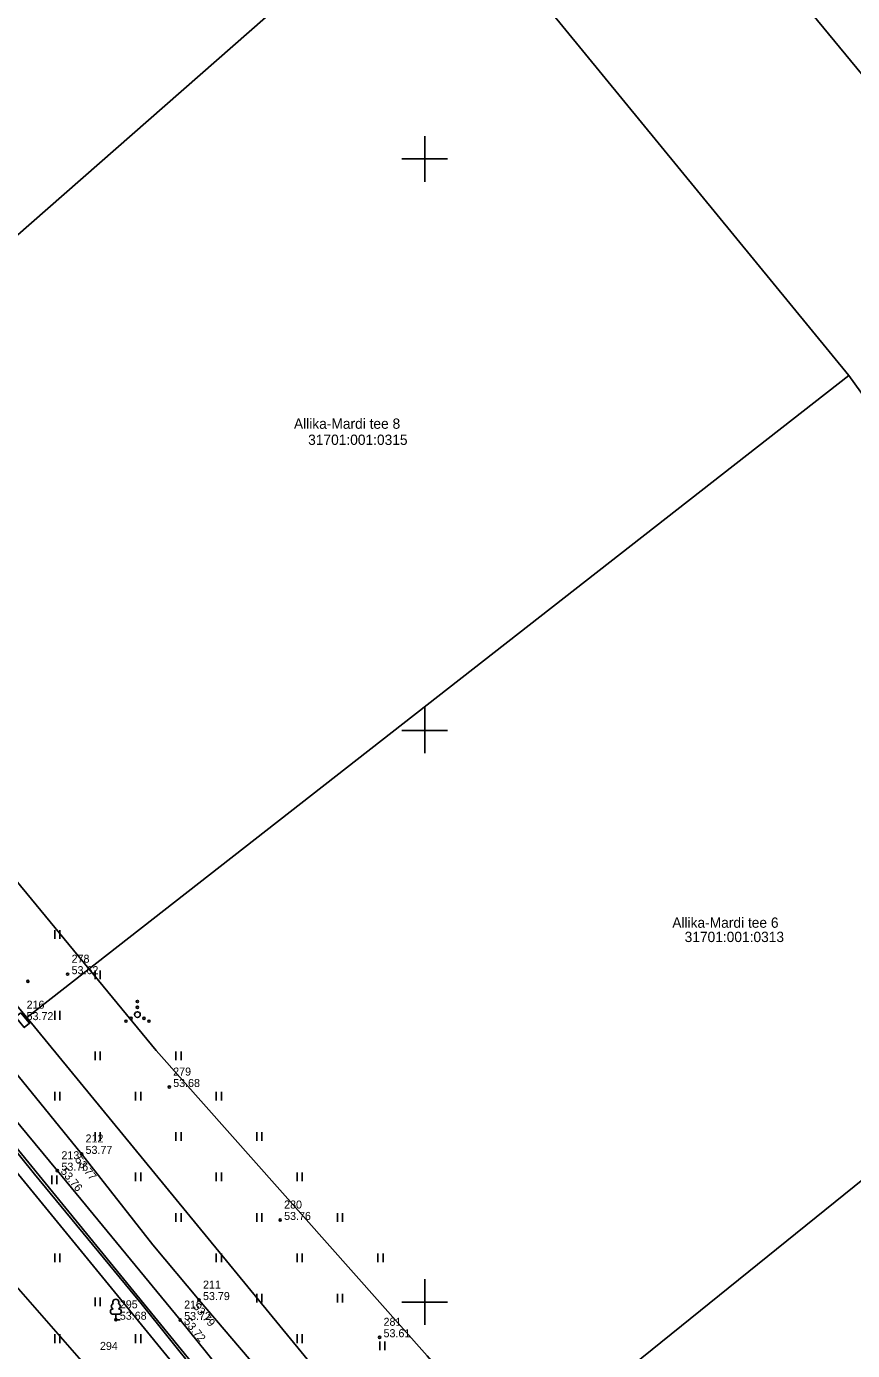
# Model space of a CAD drawing. Extents: x 538599 to 541973, y 6559689 to 6564516.
# Drawn here: x 540465.1 to 540537.4, y 6561345.8 to 6561461.6 of the extents above; entities that cross this region are included whole.
import ezdxf

# ---------------------------------------------------------------- set-up
doc = ezdxf.new("R2010")
doc.units = 0
for name, color, linetype in [('ELRAJATISMP', 7, 'Continuous'), ('HALJASTUS', 7, 'Continuous'), ('KORGUS-EH2000', 7, 'Continuous'), ('KPKAABEL', 7, 'Continuous'), ('MOOTKORG-EH2000', 7, 'Continuous'), ('MOOTMPUNKT', 7, 'Continuous'), ('MOOTNR', 7, 'Continuous'), ('MOOTPIIR', 7, 'Continuous'), ('MPKAABEL', 7, 'Continuous'), ('PIIR', 7, 'Continuous'), ('PUU', 7, 'Continuous'), ('TEE', 7, 'Continuous'), ('VORK', 7, 'Continuous')]:
    doc.layers.add(name, color=color, linetype=linetype)

msp = doc.modelspace()

# ---------------------------------------------------------------- linework, layer by layer
at = {"layer": 'ELRAJATISMP'}
msp.add_lwpolyline([(540464.65, 6561375.31), (540465.41, 6561374.39), (540464.94, 6561374.01), (540464.19, 6561374.94)], close=True, dxfattribs=at)
at = {"layer": 'HALJASTUS'}
for p, q in [((540467.61, 6561382.53), (540467.61, 6561381.77)), ((540468.07, 6561382.53), (540468.07, 6561381.77)), ((540471.15, 6561379), (540471.15, 6561378.23)), ((540471.6, 6561379), (540471.6, 6561378.23)), ((540467.61, 6561375.46), (540467.61, 6561374.7)), ((540468.07, 6561375.46), (540468.07, 6561374.7)), ((540471.15, 6561371.92), (540471.15, 6561371.16)), ((540471.6, 6561371.92), (540471.6, 6561371.16)), ((540478.22, 6561371.92), (540478.22, 6561371.16)), ((540478.67, 6561371.92), (540478.67, 6561371.16)), ((540467.61, 6561368.39), (540467.61, 6561367.63)), ((540468.07, 6561368.39), (540468.07, 6561367.63)), ((540474.68, 6561368.39), (540474.68, 6561367.63)), ((540475.14, 6561368.39), (540475.14, 6561367.63)), ((540481.75, 6561368.39), (540481.75, 6561367.63)), ((540482.21, 6561368.39), (540482.21, 6561367.63)), ((540471.15, 6561364.85), (540471.15, 6561364.09)), ((540471.6, 6561364.85), (540471.6, 6561364.09)), ((540478.22, 6561364.85), (540478.22, 6561364.09)), ((540478.67, 6561364.85), (540478.67, 6561364.09)), ((540485.29, 6561364.85), (540485.29, 6561364.09)), ((540485.74, 6561364.85), (540485.74, 6561364.09)), ((540467.35, 6561361.06), (540467.35, 6561360.3)), ((540467.8, 6561361.06), (540467.8, 6561360.3)), ((540474.68, 6561361.32), (540474.68, 6561360.56)), ((540475.14, 6561361.32), (540475.14, 6561360.56)), ((540481.75, 6561361.32), (540481.75, 6561360.56)), ((540482.21, 6561361.32), (540482.21, 6561360.56)), ((540488.82, 6561361.32), (540488.82, 6561360.56)), ((540489.28, 6561361.32), (540489.28, 6561360.56)), ((540478.22, 6561357.78), (540478.22, 6561357.02)), ((540478.67, 6561357.78), (540478.67, 6561357.02)), ((540485.29, 6561357.78), (540485.29, 6561357.02)), ((540485.74, 6561357.78), (540485.74, 6561357.02)), ((540492.36, 6561357.78), (540492.36, 6561357.02)), ((540492.81, 6561357.78), (540492.81, 6561357.02)), ((540467.61, 6561354.25), (540467.61, 6561353.49)), ((540468.07, 6561354.25), (540468.07, 6561353.49)), ((540481.75, 6561354.25), (540481.75, 6561353.49)), ((540482.21, 6561354.25), (540482.21, 6561353.49)), ((540488.82, 6561354.25), (540488.82, 6561353.49)), ((540489.28, 6561354.25), (540489.28, 6561353.49)), ((540495.89, 6561354.25), (540495.89, 6561353.49)), ((540496.35, 6561354.25), (540496.35, 6561353.49)), ((540471.15, 6561350.41), (540471.15, 6561349.65)), ((540471.6, 6561350.41), (540471.6, 6561349.65)), ((540485.29, 6561350.71), (540485.29, 6561349.95)), ((540485.74, 6561350.71), (540485.74, 6561349.95)), ((540492.36, 6561350.71), (540492.36, 6561349.95)), ((540492.81, 6561350.71), (540492.81, 6561349.95)), ((540467.61, 6561347.18), (540467.61, 6561346.41)), ((540468.07, 6561347.18), (540468.07, 6561346.41)), ((540474.68, 6561347.18), (540474.68, 6561346.41)), ((540475.14, 6561347.18), (540475.14, 6561346.41)), ((540488.82, 6561347.18), (540488.82, 6561346.41)), ((540489.28, 6561347.18), (540489.28, 6561346.41)), ((540496.05, 6561346.56), (540496.05, 6561345.8)), ((540496.51, 6561346.56), (540496.51, 6561345.8))]:
    msp.add_line(p, q, dxfattribs=at)
for centre, radius in [((540465.26, 6561378.06), 0.1), ((540474.85, 6561375.14), 0.25), ((540474.85, 6561376.29), 0.1), ((540474.85, 6561375.79), 0.1), ((540473.85, 6561374.57), 0.1), ((540474.29, 6561374.82), 0.1), ((540475.42, 6561374.82), 0.1), ((540475.85, 6561374.57), 0.1)]:
    msp.add_circle(centre, radius, dxfattribs=at)
at = {"layer": 'KORGUS-EH2000'}
for centre in [(540468.74, 6561378.68), (540477.64, 6561368.81), (540469.96, 6561362.96), (540467.85, 6561361.49), (540487.34, 6561357.18), (540480.24, 6561350.17), (540478.59, 6561348.43), (540496.04, 6561346.92)]:
    msp.add_circle(centre, 0.1, dxfattribs=at)
at = {"layer": 'KPKAABEL'}
msp.add_lwpolyline([(540612.71, 6561251.64), (540589.75, 6561235.92), (540575.11, 6561226.32), (540574.31, 6561226.49), (540572.81, 6561227.65), (540566.99, 6561234.12), (540563.29, 6561239.03), (540553.8, 6561251.29), (540538.41, 6561271.22), (540529.49, 6561282.51), (540526.27, 6561286.88), (540510.56, 6561306.2), (540484.62, 6561338.57), (540463.55, 6561364.4), (540438.89, 6561393.7), (540425.44, 6561409.21), (540424.92, 6561409.46), (540423.73, 6561408.81), (540421.72, 6561406.34), (540419.82, 6561404.72)], dxfattribs=at)
at = {"layer": 'MOOTMPUNKT'}
for centre in [(540468.74, 6561378.68), (540477.64, 6561368.81), (540469.96, 6561362.96), (540467.85, 6561361.49), (540487.34, 6561357.18), (540480.24, 6561350.17), (540472.96, 6561348.45), (540478.59, 6561348.43), (540496.04, 6561346.92)]:
    msp.add_circle(centre, 0.1, dxfattribs=at)
at = {"layer": 'MOOTPIIR'}
for points in [[(540611.81, 6561347.63), (540600.55, 6561344.05), (540588.99, 6561338.31), (540579.51, 6561329.75), (540567.37, 6561324.71), (540557.3, 6561315.5), (540537.55, 6561303.29), (540525.23, 6561316.05), (540500.22, 6561345.28), (540476.49, 6561372), (540449.03, 6561405.28), (540428.79, 6561428.29), (540413.02, 6561448.22), (540405.1, 6561459.89), (540393.81, 6561473.15)], [(540384.89, 6561443.84), (540403.97, 6561422.47), (540424.3, 6561399.7), (540444.64, 6561376.93), (540453.18, 6561363.99), (540470.99, 6561343.69), (540492.69, 6561318.98), (540511.77, 6561294.34), (540521.97, 6561279.18), (540525.59, 6561267.95), (540536.49, 6561252.79), (540542.77, 6561231.93), (540526.6, 6561219.05), (540510.62, 6561213.47), (540498.26, 6561199.2), (540484.56, 6561192.98), (540479.62, 6561185.62), (540478.41, 6561178.33), (540490.46, 6561165.83), (540493.58, 6561162.6), (540531.11, 6561187.91), (540582.87, 6561222.82), (540621.74, 6561247.75)]]:
    msp.add_lwpolyline(points, dxfattribs=at)
at = {"layer": 'MPKAABEL'}
msp.add_lwpolyline([(540496.22, 6561323.66), (540475.17, 6561349.87), (540465.85, 6561361.18), (540459.23, 6561369.37), (540458.44, 6561368.9), (540458.85, 6561369.82), (540450.37, 6561379.81), (540440.39, 6561391.62), (540426.57, 6561407.61), (540425.32, 6561409.05), (540424.93, 6561409.23), (540424.03, 6561408.75), (540421.85, 6561406.21), (540419.93, 6561404.6)], dxfattribs=at)
at = {"layer": 'PIIR'}
for points in [[(540290.72, 6561746.68), (540427.24, 6561588.74), (540493.94, 6561511.13), (540543.58, 6561450.93), (540540.24, 6561448.03), (540578.89, 6561396.62), (540600.99, 6561365.08), (540659.54, 6561279.7), (540697.59, 6561212.89), (540728.6, 6561157.63), (540756.94, 6561107.21), (540762.6, 6561098.5), (540765.3, 6561101.59), (540815.83, 6561019.53), (540863.6, 6560935.22), (540880.61, 6560910.09), (540903.4, 6560875.14), (540927.11, 6560842.51), (540955.71, 6560805.99), (540982.2, 6560772.63), (541049.12, 6560693.03)], [(541045.65, 6560666.8), (540964.7, 6560765.19), (540868.94, 6560895.75), (540756.19, 6561084.56), (540744.95, 6561099.98), (540716.4, 6561150.76), (540687.02, 6561204.55), (540646.74, 6561272.89), (540640.63, 6561283.66), (540606.26, 6561333.96), (540569.6, 6561385.93), (540537.11, 6561431.06), (540500.82, 6561475.34), (540460.86, 6561522.64), (540423.13, 6561566.69), (540380.29, 6561616.49), (540342.1, 6561660.8)]]:
    msp.add_lwpolyline(points, dxfattribs=at)
for points in [[(540493.94, 6561511.13), (540576.02, 6561585.01), (540701.8, 6561446.25), (540600.99, 6561365.08), (540578.89, 6561396.62), (540540.24, 6561448.03), (540543.58, 6561450.93)], [(540491.21, 6561183.5), (540566.07, 6561233.36), (540528.84, 6561281.85), (540494.34, 6561324.62), (540458.27, 6561368.69), (540424.68, 6561408.57), (540384.55, 6561455.73), (540346.17, 6561499.11), (540330.12, 6561517.14), (540337.36, 6561523.32), (540348.28, 6561532.96), (540364.11, 6561514.94), (540353.14, 6561505.27), (540391.51, 6561461.86), (540431.74, 6561414.74), (540465.17, 6561374.89), (540501.31, 6561330.86), (540535.92, 6561287.97), (540573.77, 6561238.75), (540640.63, 6561283.66), (540646.74, 6561272.89), (540499, 6561174.36)], [(540391.51, 6561461.86), (540460.86, 6561522.64), (540500.82, 6561475.34), (540431.74, 6561414.74)], [(540431.74, 6561414.74), (540500.82, 6561475.34), (540537.11, 6561431.06), (540465.17, 6561374.89)], [(540465.17, 6561374.89), (540537.11, 6561431.06), (540569.6, 6561385.93), (540501.31, 6561330.86)], [(540501.31, 6561330.86), (540569.6, 6561385.93), (540606.26, 6561333.96), (540535.92, 6561287.97)], [(540384.73, 6561304.57), (540458.27, 6561368.69), (540494.34, 6561324.62), (540422.29, 6561261.69)]]:
    msp.add_lwpolyline(points, close=True, dxfattribs=at)
at = {"layer": 'PUU'}
for p, q in [((540473.2, 6561348.93), (540472.72, 6561348.93)), ((540472.96, 6561348.45), (540472.96, 6561348.93)), ((540473.34, 6561348.45), (540472.96, 6561348.45))]:
    msp.add_line(p, q, dxfattribs=at)
for centre, radius, start, end in [((540472.79, 6561349.63), 0.233, 109.0217, 253.1415), ((540472.96, 6561349.97), 0.277, 332.5799, 207.4201), ((540473.13, 6561349.63), 0.233, 286.8508, 70.9859), ((540472.72, 6561349.17), 0.238, 90.0016, 269.3953), ((540473.2, 6561349.17), 0.238, 270.6047, 89.9984)]:
    msp.add_arc(centre, radius, start, end, dxfattribs=at)
at = {"layer": 'TEE'}
for points in [[(540488.15, 6561336.58), (540478.59, 6561348.43), (540467.85, 6561361.49), (540459.32, 6561371.76), (540451.23, 6561381.75), (540441.06, 6561393.63), (540438.74, 6561396.54), (540432.54, 6561404.86), (540428.83, 6561409.26), (540422.19, 6561416.81), (540412.69, 6561428.77), (540402.74, 6561440.04), (540395.61, 6561447.09), (540392.51, 6561450.44), (540382.51, 6561461.31)], [(540388.6, 6561459.28), (540394.61, 6561452.94), (540404.96, 6561441.5), (540414.41, 6561430.92), (540424.76, 6561418.49), (540434.32, 6561406.77), (540435.95, 6561404.71), (540443.75, 6561395.53), (540453.23, 6561383.82), (540461.24, 6561373.67), (540469.96, 6561362.96), (540476.2, 6561354.99), (540480.24, 6561350.17), (540490.34, 6561338.33)]]:
    msp.add_lwpolyline(points, dxfattribs=at)
at = {"layer": 'VORK'}
for p, q in [((540500, 6561452), (540500, 6561448)), ((540498, 6561450), (540502, 6561450)), ((540500, 6561402), (540500, 6561398)), ((540498, 6561400), (540502, 6561400)), ((540500, 6561352), (540500, 6561348)), ((540498, 6561350), (540502, 6561350))]:
    msp.add_line(p, q, dxfattribs=at)

# ---------------------------------------------------------------- texts
at = {"layer": 'KORGUS-EH2000'}
for s, p in [('53.62', (540469.09, 6561378.68)), ('53.68', (540477.98, 6561368.81)), ('53.76', (540487.69, 6561357.18)), ('53.61', (540496.39, 6561346.92))]:
    msp.add_text(s, height=0.7, dxfattribs=at).set_placement(p)
for s, rotation, p in [('53.77', 308.0609, (540469.34, 6561362.42)), ('53.76', 309.4141, (540468.08, 6561361.4)), ('53.79', 310.4823, (540479.67, 6561349.56)), ('53.72', 308.9107, (540478.87, 6561348.26))]:
    msp.add_text(s, height=0.7, rotation=rotation, dxfattribs=at).set_placement(p)
at = {"layer": 'MOOTKORG-EH2000'}
for s, p in [('53.62', (540469.09, 6561378.68)), ('53.72', (540465.15, 6561374.66)), ('53.68', (540477.98, 6561368.81)), ('53.77', (540470.31, 6561362.96)), ('53.76', (540468.2, 6561361.49)), ('53.76', (540487.69, 6561357.18)), ('53.79', (540480.59, 6561350.17)), ('53.68', (540473.31, 6561348.45)), ('53.72', (540478.94, 6561348.43)), ('53.61', (540496.39, 6561346.92))]:
    msp.add_text(s, height=0.7, dxfattribs=at).set_placement(p)
at = {"layer": 'MOOTNR'}
for s, p in [('278', (540469.09, 6561379.68)), ('216', (540465.15, 6561375.66)), ('279', (540477.98, 6561369.81)), ('212', (540470.31, 6561363.96)), ('213', (540468.2, 6561362.49)), ('280', (540487.69, 6561358.18)), ('211', (540480.59, 6561351.17)), ('295', (540473.31, 6561349.45)), ('210', (540478.94, 6561349.43)), ('281', (540496.39, 6561347.92)), ('294', (540471.57, 6561345.81))]:
    msp.add_text(s, height=0.7, dxfattribs=at).set_placement(p)
at = {"layer": 'PIIR'}
for s, p in [('Allika-Mardi tee 8', (540488.55, 6561426.39)), ('31701:001:0315', (540489.79, 6561424.98)), ('Allika-Mardi tee 6', (540521.66, 6561382.74)), ('31701:001:0313', (540522.74, 6561381.49))]:
    msp.add_text(s, height=0.9, rotation=0, dxfattribs=at).set_placement(p)

doc.saveas('drawing.dxf')
